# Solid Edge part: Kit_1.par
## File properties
Sűrűség: 0,000 kg/m^3
Pontosság: 0,990
Author: ahadarics
Last saved by: ahadarics
Revision: 76
Username: ahadarics
Dokumentum tartalom típus: 0
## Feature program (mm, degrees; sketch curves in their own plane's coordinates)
base feature "unnamed BaseFeature 1"
thread "unnamed Thread 1"
chamfer "unnamed Chamfer 1"
sketch for "Furat_1" plane through (0, -49.25, 13.5) normal (0, 0, 1) x-axis (0, 1, 0)
  hole centre (0.25, 0) bore radius 4.283
hole "Furat_1" nominal diameter 9.728 finite  ThreadDepth = 7.5 mm
chamfer "Letörés_2" setback 0.7
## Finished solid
Body 1: solid body, 49 faces, 55 edges, 9 vertices.
  Faces by surface: cylinder 16, plane 15, cone 11, torus 7
  Edges by curve: circle 46, line 7, intersection 2
Bounding box of the edges (mm; curved faces can reach further): 30.000 x 39.500 x 28.500, from (-15, -79, -15) to (15, -39.5, 13.5).
Cylindrical faces by radius (mm): R4.283 x3, R5.25 x1, R5.55 x1, R7 x3, R7.05 x1, R8.05 x1, R8.1 x1, R9.85 x1, R11 x2, R13.5 x1, R15 x1
Conical faces (half-angle, radius in mm at the cone's reference point): 0.1788 deg R6.7706 x1, 15 deg R8.05 x1, 17.2279 deg R5.55 x1, 19.7315 deg R5.0176 x1, 21.0856 deg R5.55 x1, 21.5244 deg R6.2703 x1, 45 deg R4.283 x1, 45 deg R7.15 x1, 45 deg R7.2 x1, 45 deg R11 x1, 60 deg R10.425 x1
Toroidal faces (ring radius, tube radius in mm): R5.2 r0.2 x1, R5.3 r0.3 x1, R6.6424 r0.4 x1, R6.85 r0.2 x1, R7.85 r0.2 x1, R7.9 r0.2 x2
Planar faces by outward normal: +y 5, +z 2, -y 8
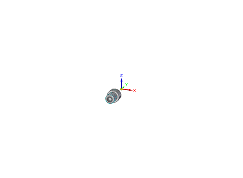
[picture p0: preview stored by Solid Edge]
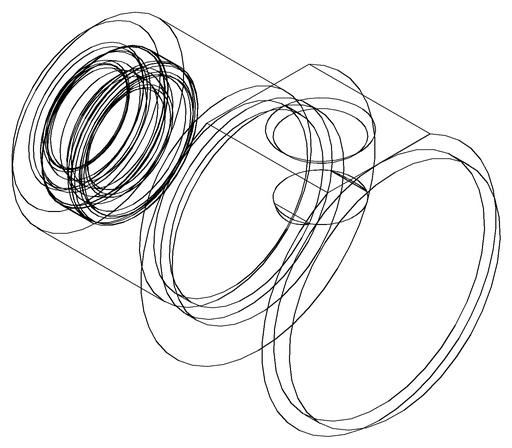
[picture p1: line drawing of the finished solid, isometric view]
